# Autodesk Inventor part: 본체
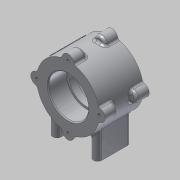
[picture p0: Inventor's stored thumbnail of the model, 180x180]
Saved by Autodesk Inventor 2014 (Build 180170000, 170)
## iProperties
Created: 2015-03
Part Number: 본체
Material: 알루미늄 6061
Document SubType Name: Modeling
Designer: MYHOME
Mass: 450.776 g
Surface Area: 332.745 cm^2
Volume: 166.338 cm^3
Density: 2.71 g/cm^3
Appearance: 알루미늄 - 평지
Author: MYHOME
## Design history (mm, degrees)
sketch "스케치2"
  geometry: C1 r 37 at (0, 0); 1 further point
  constraints: 1 centre point, 1 coincident
  dimensions: "d0" = 74 diameter of C1
extrude "돌출1" new body sketch "스케치2" stored distance "d1" = 52; taper "d2" = 0 deg
sketch "스케치3"
  geometry: C1 r 7 at (0, 37); C2 r 7 at (-37, 0); C3 r 7 at (0, -37); C4 r 7 at (37, 0); A1 r 37 centre (0, 0) between (0, 37) and (-37, 0) reference
  constraints: 4 centre point, 4 point on circle
  dimensions: "d3" = 14 diameter of C1; "d4" = 14 diameter of C2; "d5" = 14 diameter of C3; "d6" = 14 diameter of C4
extrude "돌출2" join sketch "스케치3" distance "d7" = 15; taper "d8" = 0 deg
fillet "모깎기1" dims "d9" = 3
fillet "모깎기2" dims "d10" = 3
sketch "스케치4"
  geometry: A1 r 7 centre (0, 37) between (6.889, 38.239) and (-6.889, 38.239) reference; A2 r 7 centre (-37, 0) between (-38.239, 6.889) and (-38.239, -6.889) reference; A3 r 7 centre (0, -37) between (-6.889, -38.239) and (6.889, -38.239) reference; A4 r 7 centre (37, 0) between (38.239, -6.889) and (38.239, 6.889) reference; 4 further points
  constraints: 4 coincident
hole "구멍1" sketch "스케치4" at (-37, 0), (0, 37), (37, 0), (0, -37) diameter "d11" = 3.242; stored, may be unused: countersink angle "d15" = 90 deg, drill point angle "d17" = 118 deg; dims "d12" = 8, "d13" = 4, "d14" = 2, "d16" = 11
node "작업 평면1"
sketch "스케치5"
  geometry: L1 (24, 15)-(24, -15); L2 (19, 15)-(19, -15); L3 (29, -15)-(29, 15); A1 r 5 centre (24, 15) between (29, 15) and (19, 15); A2 r 5 centre (24, -15) between (19, -15) and (29, -15); 2 further points
  constraints: 8 end point, 4 point on circle, 4 tangent, 2 centre point, 1 horizontal alignment, 1 midpoint, 1 parallel, 1 vertical
  dimensions: "d19" = 10 distance between parallel lines of L3 L2; "d20" = 40 dimension on A2 A1; "d21" = 24 distance from line of point (0, 0) L1
extrude "돌출3" join sketch "스케치5" stored distance "d22" = 15; taper "d23" = 0 deg
fillet "모깎기3" dims "d24" = 3
sketch "스케치6"
  geometry: A1 r 5 centre (24, -15) between (19, -15) and (29, -15) reference; A2 r 5 centre (24, 15) between (29, 15) and (19, 15) reference; 3 further points
  constraints: 2 coincident
hole "구멍2" sketch "스케치6" at (24, 15), (24, -15) diameter "d25" = 4.134; stored, may be unused: countersink angle "d29" = 90 deg, drill point angle "d31" = 118 deg; dims "d26" = 6, "d27" = 4, "d28" = 2, "d30" = 8
sketch "스케치8"
  geometry: C1 r 23.5 at (0, 0); A1 r 37 centre (0, 0) between (9.104, -35.863) and (35.863, -9.104) reference
  constraints: 1 centre point, 1 coincident
  dimensions: "d32" = 47 diameter of C1
extrude "돌출4" cut sketch "스케치8" distance "d33" = 22; taper "d34" = 0 deg
hole "구멍3" diameter "d37" = 42; stored, may be unused: countersink angle "d41" = 90 deg, drill point angle "d43" = 0 deg; dims "d35" = 10, "d36" = 10, "d38" = 6, "d39" = 47, "d40" = 22, "d42" = 8
chamfer "모따기1" distance "d44" = 1; stored, may be unused: second distance "d45" = 2, angle "d46" = 45 deg
fillet "모깎기4" dims "d47" = 0.3
sketch "스케치9"
  geometry: L1 (0, 0)-(37, 0); L2 (0, 0)-(26.163, 26.163); A1 r 37 centre (0, 0) between (35.863, 9.104) and (9.104, 35.863) reference; A2 r 37 centre (0, 0) between (36.913, -2.543) and (36.913, 2.543) reference; 2 further points
  constraints: 4 end point, 2 coincident, 2 point on circle
  dimensions: "d48" = 45 deg angle of L1 L2
node "작업 평면2"
sketch "스케치11"
  geometry: L1 (-26, 18.921)-(-26, -18.921) reference; 2 further points
  constraints: 1 coincident, 1 other
  dimensions: "d53" = 26 distance from line of L1 point (0, 0)
feature "엠보싱2" sketch "스케치11" dims "d54" = 0.5, "d55" = 0
node "솔리드1"
mirror "대칭1"
mirror "대칭2"
other parameters: "d18" = -56
